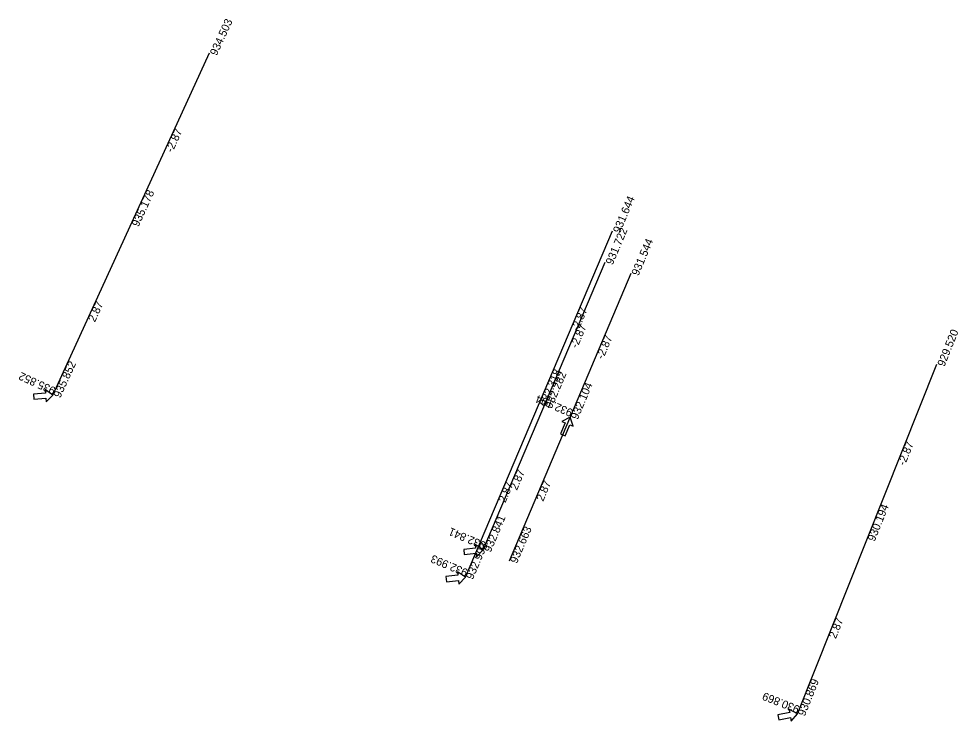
# Model space of a CAD drawing. Extents: x 4435 to 1613579, y 3750 to 1095560.
# Drawn here: x 1613461.9 to 1613579.2, y 1095471.9 to 1095559.6 of the extents above; entities that cross this region are included whole.
import ezdxf

# ---------------------------------------------------------------- set-up
doc = ezdxf.new("R2010")
doc.units = 0
doc.layers.add('Default', color=7, linetype='Continuous')

msp = doc.modelspace()

# ---------------------------------------------------------------- linework, layer by layer
at = {"layer": 'Default'}
for p, q in [((1613466.13, 1095512.6), (1613485.67, 1095555.35)), ((1613517.64, 1095489.89), (1613536.02, 1095533.15)), ((1613519.87, 1095493.29), (1613535.11, 1095529.2)), ((1613523.16, 1095491.9), (1613538.33, 1095527.83)), ((1613559.11, 1095472.81), (1613576.54, 1095516.46))]:
    msp.add_line(p, q, dxfattribs=at)
for points in [[(1613466.13, 1095512.6), (1613465.15, 1095513.3), (1613465.19, 1095512.85), (1613463.69, 1095512.73), (1613463.74, 1095512.09), (1613465.24, 1095512.21), (1613465.28, 1095511.76)], [(1613530.75, 1095509.87), (1613529.68, 1095509.32), (1613530.09, 1095509.14), (1613529.51, 1095507.76), (1613530.1, 1095507.51), (1613530.69, 1095508.89), (1613531.1, 1095508.72)], [(1613519.87, 1095493.29), (1613518.87, 1095493.95), (1613518.92, 1095493.51), (1613517.43, 1095493.34), (1613517.51, 1095492.7), (1613519, 1095492.87), (1613519.05, 1095492.42)], [(1613517.64, 1095489.89), (1613516.64, 1095490.56), (1613516.7, 1095490.11), (1613515.2, 1095489.94), (1613515.28, 1095489.3), (1613516.77, 1095489.47), (1613516.82, 1095489.02)], [(1613559.11, 1095472.81), (1613558.06, 1095473.4), (1613558.15, 1095472.96), (1613556.67, 1095472.68), (1613556.79, 1095472.05), (1613558.27, 1095472.33), (1613558.35, 1095471.88)]]:
    msp.add_lwpolyline(points, close=True, dxfattribs=at)

# ---------------------------------------------------------------- texts
for s, rotation, p in [('934.503', 65.4351, (1613486.58, 1095554.93)), ('-2.87', 65.4351, (1613481.05, 1095542.83)), ('935.178', 65.4351, (1613476.81, 1095533.56)), ('931.644', 66.9907, (1613536.94, 1095532.76)), ('931.722', 67.0108, (1613536.03, 1095528.8)), ('931.544', 67.1096, (1613539.25, 1095527.44)), ('2.87', 65.4351, (1613471.37, 1095521.66)), ('-2.87', 66.9907, (1613531.73, 1095520.51)), ('-2.87', 67.0108, (1613531.61, 1095518.39)), ('929.520', 68.23, (1613577.47, 1095516.09)), ('-2.87', 67.1096, (1613534.85, 1095517.02)), ('935.852', 65.4351, (1613467.04, 1095512.18)), ('932.318', 66.9907, (1613527.75, 1095511.13)), ('935.852', 155.4351, (1613466.55, 1095513.51)), ('932.282', 67.0108, (1613528.41, 1095510.85)), ('932.104', 67.1096, (1613531.67, 1095509.48)), ('932.104', 157.1096, (1613531.14, 1095510.79)), ('-2.87', 68.23, (1613572.53, 1095503.73)), ('2.87', 67.0108, (1613524.08, 1095500.66)), ('2.87', 66.9907, (1613522.64, 1095499.1)), ('2.87', 67.1096, (1613527.36, 1095499.27)), ('930.194', 68.23, (1613568.76, 1095494.26)), ('932.841', 67.0108, (1613520.8, 1095492.9)), ('932.841', 157.0108, (1613520.27, 1095494.21)), ('932.663', 67.1096, (1613524.08, 1095491.51)), ('932.993', 66.9907, (1613518.57, 1095489.5)), ('932.993', 156.9907, (1613518.04, 1095490.81)), ('2.87', 68.23, (1613563.91, 1095482.12)), ('930.869', 68.23, (1613560.04, 1095472.44)), ('930.869', 158.23, (1613559.48, 1095473.74))]:
    msp.add_text(s, height=1, rotation=rotation, dxfattribs=at).set_placement(p)

doc.saveas('drawing.dxf')
